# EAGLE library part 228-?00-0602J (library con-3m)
Zero Insertion Force Socked Source: http://www.3M.com/ehpd
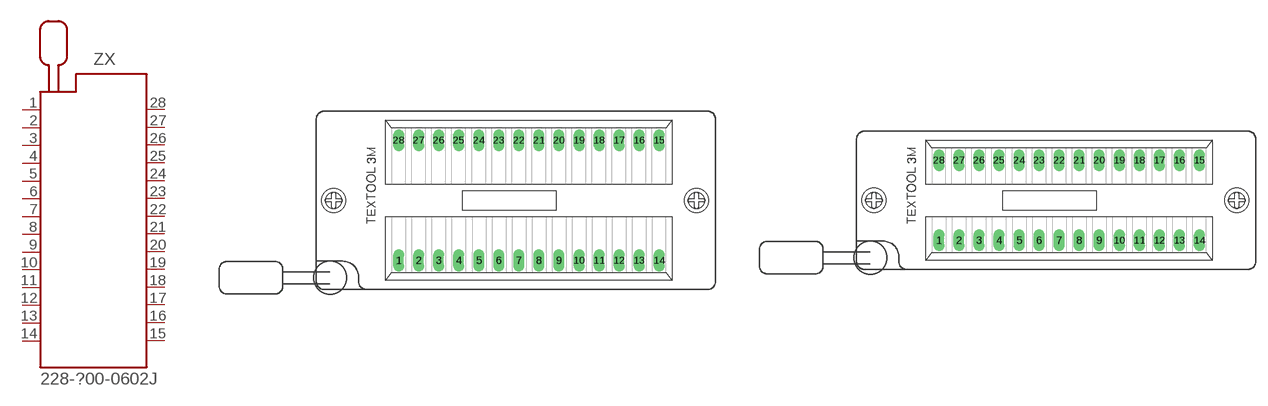
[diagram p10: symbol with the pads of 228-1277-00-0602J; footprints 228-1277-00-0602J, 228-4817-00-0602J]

Designator prefix ZX

## 228-1277-00-0602J (MF: 3M; MPN: 228-1277-00-0602J; OC_FARNELL: 9897356; OC_NEWARK: 85K7825)  [228-1277-00-0602J]
1  1  pas
2  2  pas
3  3  pas
4  4  pas
5  5  pas
6  6  pas
7  7  pas
8  8  pas
9  9  pas
10  10  pas
11  11  pas
12  12  pas
13  13  pas
14  14  pas
15  15  pas
16  16  pas
17  17  pas
18  18  pas
19  19  pas
20  20  pas
21  21  pas
22  22  pas
23  23  pas
24  24  pas
25  25  pas
26  26  pas
27  27  pas
28  28  pas

## 228-4817-00-0602J (MF: 3M; MPN: 228-4817-00-0602J; OC_FARNELL: 1252775; OC_NEWARK: 85K7834)  [228-4817-00-0602J]
Pads as for 228-1277-00-0602J

## Footprint 228-1277-00-0602J (pad centres in mm)
3M TEXTOOL 28 pol. DIP Lever actuated zero insertion force mechanism Hersteller: 3M TEXTOOL Herstellerbez.: 228-1277-00-0602J Farnell Best.-Nr.: 4665405 Source: http://www.3M.com/ehpd
drill 0.9 long: 1 -16.51,-7.62; 2 -13.97,-7.62; 3 -11.43,-7.62; 4 -8.89,-7.62; 5 -6.35,-7.62; 6 -3.81,-7.62; 7 -1.27,-7.62; 8 1.27,-7.62; 9 3.81,-7.62; 10 6.35,-7.62; 11 8.89,-7.62; 12 11.43,-7.62; 13 13.97,-7.62; 14 16.51,-7.62; 15 16.51,7.62; 16 13.97,7.62; 17 11.43,7.62; 18 8.89,7.62; 19 6.35,7.62; 20 3.81,7.62; 21 1.27,7.62; 22 -1.27,7.62; 23 -3.81,7.62; 24 -6.35,7.62; 25 -8.89,7.62; 26 -11.43,7.62; 27 -13.97,7.62; 28 -16.51,7.62
hole 2 at 21.24,0
hole 2 at -24.74,0

## Footprint 228-4817-00-0602J (pad centres in mm)
3M TEXTOOL 28 pol. DIP Lever actuated zero insertion force mechanism Hersteller: 3M TEXTOOL Herstellerbez.: 228-4817-00-0602J Source: http://www.3M.com/ehpd
drill 0.9 long: 1 -16.51,-5.08; 2 -13.97,-5.08; 3 -11.43,-5.08; 4 -8.89,-5.08; 5 -6.35,-5.08; 6 -3.81,-5.08; 7 -1.27,-5.08; 8 1.27,-5.08; 9 3.81,-5.08; 10 6.35,-5.08; 11 8.89,-5.08; 12 11.43,-5.08; 13 13.97,-5.08; 14 16.51,-5.08; 15 16.51,5.08; 16 13.97,5.08; 17 11.43,5.08; 18 8.89,5.08; 19 6.35,5.08; 20 3.81,5.08; 21 1.27,5.08; 22 -1.27,5.08; 23 -3.81,5.08; 24 -6.35,5.08; 25 -8.89,5.08; 26 -11.43,5.08; 27 -13.97,5.08; 28 -16.51,5.08
hole 2 at 21.24,0
hole 2 at -24.74,0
